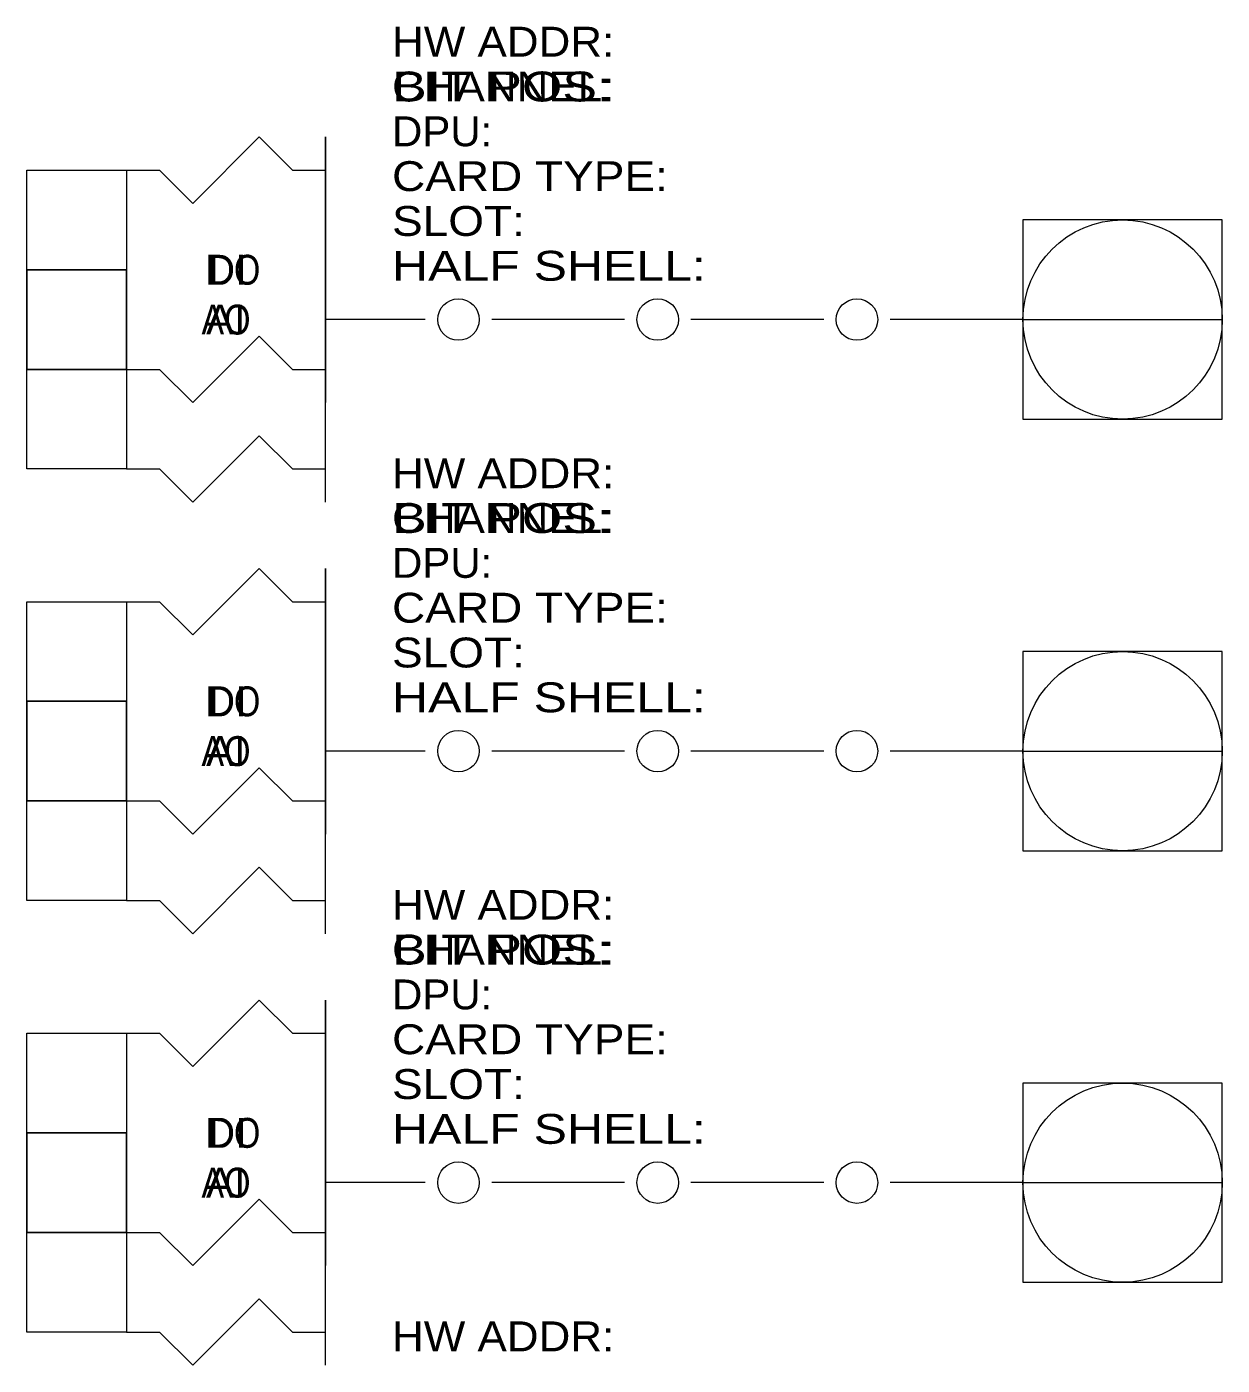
# Model space of a CAD drawing. Extents: x 0.958 to 1.258, y 0.171 to 0.832.
# Drawn here: x 0.9583 to 1.2583, y 0.4958 to 0.8318 of the extents above; entities that cross this region are included whole.
import ezdxf
from ezdxf.enums import TextEntityAlignment as Align

# ---------------------------------------------------------------- set-up
doc = ezdxf.new("R2010")
doc.units = 0
doc.header["$LTSCALE"] = 0.003
for name, color, linetype, lineweight in [('1', 7, 'Continuous', 13), ('10', 7, 'Continuous', 13), ('11', 7, 'Continuous', 13), ('12', 7, 'Continuous', 13), ('13', 7, 'Continuous', 13), ('14', 7, 'Continuous', 13), ('19', 7, 'Continuous', 13), ('2', 7, 'Continuous', 13), ('20', 7, 'Continuous', 13), ('21', 7, 'Continuous', 13), ('22', 7, 'Continuous', 13), ('23', 7, 'Continuous', 13), ('24', 7, 'Continuous', 13), ('29', 7, 'Continuous', 13), ('3', 7, 'Continuous', 13), ('30', 7, 'Continuous', 13), ('39', 7, 'Continuous', 13), ('4', 7, 'Continuous', 13), ('40', 7, 'Continuous', 13), ('9', 7, 'Continuous', 13)]:
    doc.layers.add(name, color=color, linetype=linetype, lineweight=lineweight)

msp = doc.modelspace()

# ---------------------------------------------------------------- linework, layer by layer
at = {"layer": '1'}
for p, q in [((1.033333, 0.804166), (1.033333, 0.7375)), ((0.958333, 0.770833), (0.958333, 0.745833)), ((0.983333, 0.745833), (0.983333, 0.770833)), ((0.958333, 0.745833), (0.983333, 0.745833))]:
    msp.add_line(p, q, dxfattribs=at)
for points in [[(0.983333, 0.795833), (0.991666, 0.795833), (1, 0.7875), (1.016666, 0.804166), (1.025, 0.795833), (1.033333, 0.795833)], [(0.983333, 0.745833), (0.991666, 0.745833), (1, 0.7375), (1.016666, 0.754166), (1.025, 0.745833), (1.033333, 0.745833)]]:
    msp.add_lwpolyline(points, dxfattribs=at)
msp.add_lwpolyline([(0.958333, 0.795833), (0.983333, 0.795833), (0.983333, 0.770833), (0.958333, 0.770833)], close=True, dxfattribs=at)
at = {"layer": '10'}
for p, q in [((1.058333, 0.758333), (1.033333, 0.758333)), ((1.108333, 0.758333), (1.075, 0.758333)), ((1.158333, 0.758333), (1.125, 0.758333)), ((1.208333, 0.758333), (1.175, 0.758333)), ((1.208333, 0.758333), (1.258333, 0.758333))]:
    msp.add_line(p, q, dxfattribs=at)
msp.add_lwpolyline([(1.208333, 0.783333), (1.208333, 0.733333), (1.258333, 0.733333), (1.258333, 0.783333)], close=True, dxfattribs=at)
for centre, radius in [((1.233333, 0.758333), 0.025), ((1.066666, 0.758333), 0.005208), ((1.116666, 0.758333), 0.005208), ((1.166666, 0.758333), 0.005208)]:
    msp.add_circle(centre, radius, dxfattribs=at)
at = {"layer": '11'}
msp.add_line((1.033333, 0.695833), (1.033333, 0.629166), dxfattribs=at)
for points in [[(0.983333, 0.6875), (0.991666, 0.6875), (1, 0.679166), (1.016666, 0.695833), (1.025, 0.6875), (1.033333, 0.6875)], [(0.958333, 0.6625), (0.958333, 0.6375), (0.983333, 0.6375), (0.983333, 0.6625)], [(0.983333, 0.6375), (0.991666, 0.6375), (1, 0.629166), (1.016666, 0.645833), (1.025, 0.6375), (1.033333, 0.6375)]]:
    msp.add_lwpolyline(points, dxfattribs=at)
msp.add_lwpolyline([(0.958333, 0.6875), (0.983333, 0.6875), (0.983333, 0.6625), (0.958333, 0.6625)], close=True, dxfattribs=at)
at = {"layer": '12'}
for p, q in [((1.033333, 0.695833), (1.033333, 0.629166)), ((0.958333, 0.6625), (0.983333, 0.6625))]:
    msp.add_line(p, q, dxfattribs=at)
for points in [[(0.983333, 0.6875), (0.991666, 0.6875), (1, 0.679166), (1.016666, 0.695833), (1.025, 0.6875), (1.033333, 0.6875)], [(0.983333, 0.6375), (0.991666, 0.6375), (1, 0.629166), (1.016666, 0.645833), (1.025, 0.6375), (1.033333, 0.6375)]]:
    msp.add_lwpolyline(points, dxfattribs=at)
msp.add_lwpolyline([(0.958333, 0.6875), (0.983333, 0.6875), (0.983333, 0.6375), (0.958333, 0.6375)], close=True, dxfattribs=at)
at = {"layer": '13'}
for p, q in [((1.033333, 0.604166), (1.033333, 0.695833)), ((0.958333, 0.6625), (0.983333, 0.6625)), ((0.958333, 0.6375), (0.983333, 0.6375))]:
    msp.add_line(p, q, dxfattribs=at)
for points in [[(0.983333, 0.6875), (0.991666, 0.6875), (1, 0.679166), (1.016666, 0.695833), (1.025, 0.6875), (1.033333, 0.6875)], [(0.983333, 0.6125), (0.991666, 0.6125), (1, 0.604166), (1.016666, 0.620833), (1.025, 0.6125), (1.033333, 0.6125)]]:
    msp.add_lwpolyline(points, dxfattribs=at)
msp.add_lwpolyline([(0.958333, 0.6875), (0.983333, 0.6875), (0.983333, 0.6125), (0.958333, 0.6125)], close=True, dxfattribs=at)
at = {"layer": '14'}
for p, q in [((1.033333, 0.604166), (1.033333, 0.695833)), ((0.958333, 0.6625), (0.983333, 0.6625)), ((0.958333, 0.6375), (0.983333, 0.6375))]:
    msp.add_line(p, q, dxfattribs=at)
for points in [[(0.983333, 0.6875), (0.991666, 0.6875), (1, 0.679166), (1.016666, 0.695833), (1.025, 0.6875), (1.033333, 0.6875)], [(0.983333, 0.6125), (0.991666, 0.6125), (1, 0.604166), (1.016666, 0.620833), (1.025, 0.6125), (1.033333, 0.6125)]]:
    msp.add_lwpolyline(points, dxfattribs=at)
msp.add_lwpolyline([(0.958333, 0.6875), (0.983333, 0.6875), (0.983333, 0.6125), (0.958333, 0.6125)], close=True, dxfattribs=at)
at = {"layer": '19'}
for p, q in [((1.058333, 0.65), (1.033333, 0.65)), ((1.108333, 0.65), (1.075, 0.65)), ((1.158333, 0.65), (1.125, 0.65)), ((1.208333, 0.65), (1.175, 0.65)), ((1.208333, 0.65), (1.258333, 0.65))]:
    msp.add_line(p, q, dxfattribs=at)
msp.add_lwpolyline([(1.208333, 0.675), (1.208333, 0.625), (1.258333, 0.625), (1.258333, 0.675)], close=True, dxfattribs=at)
for centre, radius in [((1.233333, 0.65), 0.025), ((1.066666, 0.65), 0.005208), ((1.116666, 0.65), 0.005208), ((1.166666, 0.65), 0.005208)]:
    msp.add_circle(centre, radius, dxfattribs=at)
at = {"layer": '2'}
for p, q in [((1.033333, 0.804166), (1.033333, 0.7375)), ((0.958333, 0.770833), (0.983333, 0.770833))]:
    msp.add_line(p, q, dxfattribs=at)
for points in [[(0.983333, 0.795833), (0.991666, 0.795833), (1, 0.7875), (1.016666, 0.804166), (1.025, 0.795833), (1.033333, 0.795833)], [(0.983333, 0.745833), (0.991666, 0.745833), (1, 0.7375), (1.016666, 0.754166), (1.025, 0.745833), (1.033333, 0.745833)]]:
    msp.add_lwpolyline(points, dxfattribs=at)
msp.add_lwpolyline([(0.958333, 0.795833), (0.983333, 0.795833), (0.983333, 0.745833), (0.958333, 0.745833)], close=True, dxfattribs=at)
at = {"layer": '20'}
for p, q in [((1.058333, 0.65), (1.033333, 0.65)), ((1.108333, 0.65), (1.075, 0.65)), ((1.158333, 0.65), (1.125, 0.65)), ((1.208333, 0.65), (1.175, 0.65)), ((1.208333, 0.65), (1.258333, 0.65))]:
    msp.add_line(p, q, dxfattribs=at)
msp.add_lwpolyline([(1.208333, 0.675), (1.208333, 0.625), (1.258333, 0.625), (1.258333, 0.675)], close=True, dxfattribs=at)
for centre, radius in [((1.233333, 0.65), 0.025), ((1.066666, 0.65), 0.005208), ((1.116666, 0.65), 0.005208), ((1.166666, 0.65), 0.005208)]:
    msp.add_circle(centre, radius, dxfattribs=at)
at = {"layer": '21'}
msp.add_line((1.033333, 0.5875), (1.033333, 0.520833), dxfattribs=at)
for points in [[(0.983333, 0.579166), (0.991666, 0.579166), (1, 0.570833), (1.016666, 0.5875), (1.025, 0.579166), (1.033333, 0.579166)], [(0.958333, 0.554166), (0.958333, 0.529166), (0.983333, 0.529166), (0.983333, 0.554166)], [(0.983333, 0.529166), (0.991666, 0.529166), (1, 0.520833), (1.016666, 0.5375), (1.025, 0.529166), (1.033333, 0.529166)]]:
    msp.add_lwpolyline(points, dxfattribs=at)
msp.add_lwpolyline([(0.958333, 0.579166), (0.983333, 0.579166), (0.983333, 0.554166), (0.958333, 0.554166)], close=True, dxfattribs=at)
at = {"layer": '22'}
for p, q in [((1.033333, 0.5875), (1.033333, 0.520833)), ((0.958333, 0.554166), (0.983333, 0.554166))]:
    msp.add_line(p, q, dxfattribs=at)
for points in [[(0.983333, 0.579166), (0.991666, 0.579166), (1, 0.570833), (1.016666, 0.5875), (1.025, 0.579166), (1.033333, 0.579166)], [(0.983333, 0.529166), (0.991666, 0.529166), (1, 0.520833), (1.016666, 0.5375), (1.025, 0.529166), (1.033333, 0.529166)]]:
    msp.add_lwpolyline(points, dxfattribs=at)
msp.add_lwpolyline([(0.958333, 0.579166), (0.983333, 0.579166), (0.983333, 0.529166), (0.958333, 0.529166)], close=True, dxfattribs=at)
at = {"layer": '23'}
for p, q in [((1.033333, 0.495833), (1.033333, 0.5875)), ((0.958333, 0.554166), (0.983333, 0.554166)), ((0.958333, 0.529166), (0.983333, 0.529166))]:
    msp.add_line(p, q, dxfattribs=at)
for points in [[(0.983333, 0.579166), (0.991666, 0.579166), (1, 0.570833), (1.016666, 0.5875), (1.025, 0.579166), (1.033333, 0.579166)], [(0.983333, 0.504166), (0.991666, 0.504166), (1, 0.495833), (1.016666, 0.5125), (1.025, 0.504166), (1.033333, 0.504166)]]:
    msp.add_lwpolyline(points, dxfattribs=at)
msp.add_lwpolyline([(0.958333, 0.579166), (0.983333, 0.579166), (0.983333, 0.504166), (0.958333, 0.504166)], close=True, dxfattribs=at)
at = {"layer": '24'}
for p, q in [((1.033333, 0.495833), (1.033333, 0.5875)), ((0.958333, 0.554166), (0.983333, 0.554166)), ((0.958333, 0.529166), (0.983333, 0.529166))]:
    msp.add_line(p, q, dxfattribs=at)
for points in [[(0.983333, 0.579166), (0.991666, 0.579166), (1, 0.570833), (1.016666, 0.5875), (1.025, 0.579166), (1.033333, 0.579166)], [(0.983333, 0.504166), (0.991666, 0.504166), (1, 0.495833), (1.016666, 0.5125), (1.025, 0.504166), (1.033333, 0.504166)]]:
    msp.add_lwpolyline(points, dxfattribs=at)
msp.add_lwpolyline([(0.958333, 0.579166), (0.983333, 0.579166), (0.983333, 0.504166), (0.958333, 0.504166)], close=True, dxfattribs=at)
at = {"layer": '29'}
for p, q in [((1.058333, 0.541666), (1.033333, 0.541666)), ((1.108333, 0.541666), (1.075, 0.541666)), ((1.158333, 0.541666), (1.125, 0.541666)), ((1.208333, 0.541666), (1.175, 0.541666)), ((1.208333, 0.541666), (1.258333, 0.541666))]:
    msp.add_line(p, q, dxfattribs=at)
msp.add_lwpolyline([(1.208333, 0.566666), (1.208333, 0.516666), (1.258333, 0.516666), (1.258333, 0.566666)], close=True, dxfattribs=at)
for centre, radius in [((1.233333, 0.541666), 0.025), ((1.066666, 0.541666), 0.005208), ((1.116666, 0.541666), 0.005208), ((1.166666, 0.541666), 0.005208)]:
    msp.add_circle(centre, radius, dxfattribs=at)
at = {"layer": '3'}
for p, q in [((1.033333, 0.7125), (1.033333, 0.804166)), ((0.958333, 0.770833), (0.983333, 0.770833)), ((0.958333, 0.745833), (0.983333, 0.745833))]:
    msp.add_line(p, q, dxfattribs=at)
for points in [[(0.983333, 0.795833), (0.991666, 0.795833), (1, 0.7875), (1.016666, 0.804166), (1.025, 0.795833), (1.033333, 0.795833)], [(0.983333, 0.720833), (0.991666, 0.720833), (1, 0.7125), (1.016666, 0.729166), (1.025, 0.720833), (1.033333, 0.720833)]]:
    msp.add_lwpolyline(points, dxfattribs=at)
msp.add_lwpolyline([(0.958333, 0.795833), (0.983333, 0.795833), (0.983333, 0.720833), (0.958333, 0.720833)], close=True, dxfattribs=at)
at = {"layer": '30'}
for p, q in [((1.058333, 0.541666), (1.033333, 0.541666)), ((1.108333, 0.541666), (1.075, 0.541666)), ((1.158333, 0.541666), (1.125, 0.541666)), ((1.208333, 0.541666), (1.175, 0.541666)), ((1.208333, 0.541666), (1.258333, 0.541666))]:
    msp.add_line(p, q, dxfattribs=at)
msp.add_lwpolyline([(1.208333, 0.566666), (1.208333, 0.516666), (1.258333, 0.516666), (1.258333, 0.566666)], close=True, dxfattribs=at)
for centre, radius in [((1.233333, 0.541666), 0.025), ((1.066666, 0.541666), 0.005208), ((1.116666, 0.541666), 0.005208), ((1.166666, 0.541666), 0.005208)]:
    msp.add_circle(centre, radius, dxfattribs=at)
at = {"layer": '4'}
for p, q in [((1.033333, 0.7125), (1.033333, 0.804166)), ((0.958333, 0.770833), (0.983333, 0.770833)), ((0.958333, 0.745833), (0.983333, 0.745833))]:
    msp.add_line(p, q, dxfattribs=at)
for points in [[(0.983333, 0.795833), (0.991666, 0.795833), (1, 0.7875), (1.016666, 0.804166), (1.025, 0.795833), (1.033333, 0.795833)], [(0.983333, 0.720833), (0.991666, 0.720833), (1, 0.7125), (1.016666, 0.729166), (1.025, 0.720833), (1.033333, 0.720833)]]:
    msp.add_lwpolyline(points, dxfattribs=at)
msp.add_lwpolyline([(0.958333, 0.795833), (0.983333, 0.795833), (0.983333, 0.720833), (0.958333, 0.720833)], close=True, dxfattribs=at)
at = {"layer": '9'}
for p, q in [((1.058333, 0.758333), (1.033333, 0.758333)), ((1.108333, 0.758333), (1.075, 0.758333)), ((1.158333, 0.758333), (1.125, 0.758333)), ((1.208333, 0.758333), (1.175, 0.758333)), ((1.208333, 0.758333), (1.258333, 0.758333))]:
    msp.add_line(p, q, dxfattribs=at)
msp.add_lwpolyline([(1.208333, 0.783333), (1.208333, 0.733333), (1.258333, 0.733333), (1.258333, 0.783333)], close=True, dxfattribs=at)
for centre, radius in [((1.233333, 0.758333), 0.025), ((1.066666, 0.758333), 0.005208), ((1.116666, 0.758333), 0.005208), ((1.166666, 0.758333), 0.005208)]:
    msp.add_circle(centre, radius, dxfattribs=at)

# ---------------------------------------------------------------- texts
at = {"layer": '1', "width": 1.05}
msp.add_text('DI', height=0.0075, dxfattribs=at).set_placement((1.008291, 0.767083), align=Align.CENTER)
at = {"layer": '10'}
for s, width, p in [('HW ADDR:', 1.1, (1.05, 0.824333)), ('CHANNEL:', 1.1, (1.05, 0.813083)), ('DPU:', 1.05, (1.05, 0.801833)), ('CARD TYPE:', 1.15, (1.05, 0.790583)), ('SLOT:', 1.15, (1.05, 0.779333)), ('HALF SHELL:', 1.25, (1.05, 0.768083))]:
    msp.add_text(s, height=0.0075, dxfattribs=dict(at, width=width)).set_placement(p)
at = {"layer": '11', "width": 1.05}
msp.add_text('DI', height=0.0075, dxfattribs=at).set_placement((1.008291, 0.65875), align=Align.CENTER)
at = {"layer": '12', "width": 0.85}
msp.add_text('DO', height=0.0075, dxfattribs=at).set_placement((1.004166, 0.65875))
at = {"layer": '13', "width": 1.05}
msp.add_text('AI', height=0.0075, dxfattribs=at).set_placement((1.008291, 0.64625), align=Align.CENTER)
at = {"layer": '14', "width": 0.85}
msp.add_text('AO', height=0.0075, dxfattribs=at).set_placement((1.008333, 0.64625), align=Align.CENTER)
at = {"layer": '19'}
for s, width, p in [('HW ADDR:', 1.1, (1.05, 0.716)), ('BIT POS:', 1.3, (1.05, 0.70475)), ('DPU:', 1.05, (1.05, 0.6935)), ('CARD TYPE:', 1.15, (1.05, 0.68225)), ('SLOT:', 1.15, (1.05, 0.671)), ('HALF SHELL:', 1.25, (1.05, 0.65975))]:
    msp.add_text(s, height=0.0075, dxfattribs=dict(at, width=width)).set_placement(p)
at = {"layer": '2', "width": 0.85}
msp.add_text('DO', height=0.0075, dxfattribs=at).set_placement((1.004166, 0.767083))
at = {"layer": '20'}
for s, width, p in [('HW ADDR:', 1.1, (1.05, 0.716)), ('CHANNEL:', 1.1, (1.05, 0.70475)), ('DPU:', 1.05, (1.05, 0.6935)), ('CARD TYPE:', 1.15, (1.05, 0.68225)), ('SLOT:', 1.15, (1.05, 0.671)), ('HALF SHELL:', 1.25, (1.05, 0.65975))]:
    msp.add_text(s, height=0.0075, dxfattribs=dict(at, width=width)).set_placement(p)
at = {"layer": '21', "width": 1.05}
msp.add_text('DI', height=0.0075, dxfattribs=at).set_placement((1.008291, 0.550416), align=Align.CENTER)
at = {"layer": '22', "width": 0.85}
msp.add_text('DO', height=0.0075, dxfattribs=at).set_placement((1.004166, 0.550416))
at = {"layer": '23', "width": 1.05}
msp.add_text('AI', height=0.0075, dxfattribs=at).set_placement((1.008291, 0.537916), align=Align.CENTER)
at = {"layer": '24', "width": 0.85}
msp.add_text('AO', height=0.0075, dxfattribs=at).set_placement((1.008333, 0.537916), align=Align.CENTER)
at = {"layer": '29'}
for s, width, p in [('HW ADDR:', 1.1, (1.05, 0.607666)), ('BIT POS:', 1.3, (1.05, 0.596416)), ('DPU:', 1.05, (1.05, 0.585166)), ('CARD TYPE:', 1.15, (1.05, 0.573916)), ('SLOT:', 1.15, (1.05, 0.562666)), ('HALF SHELL:', 1.25, (1.05, 0.551416))]:
    msp.add_text(s, height=0.0075, dxfattribs=dict(at, width=width)).set_placement(p)
at = {"layer": '3', "width": 1.05}
msp.add_text('AI', height=0.0075, dxfattribs=at).set_placement((1.008291, 0.754583), align=Align.CENTER)
at = {"layer": '30'}
for s, width, p in [('HW ADDR:', 1.1, (1.05, 0.607666)), ('CHANNEL:', 1.1, (1.05, 0.596416)), ('DPU:', 1.05, (1.05, 0.585166)), ('CARD TYPE:', 1.15, (1.05, 0.573916)), ('SLOT:', 1.15, (1.05, 0.562666)), ('HALF SHELL:', 1.25, (1.05, 0.551416))]:
    msp.add_text(s, height=0.0075, dxfattribs=dict(at, width=width)).set_placement(p)
at = {"layer": '39', "width": 1.1}
msp.add_text('HW ADDR:', height=0.0075, dxfattribs=at).set_placement((1.05, 0.499333))
at = {"layer": '4', "width": 0.85}
msp.add_text('AO', height=0.0075, dxfattribs=at).set_placement((1.008333, 0.754583), align=Align.CENTER)
at = {"layer": '40', "width": 1.1}
msp.add_text('HW ADDR:', height=0.0075, dxfattribs=at).set_placement((1.05, 0.499333))
at = {"layer": '9'}
for s, width, p in [('HW ADDR:', 1.1, (1.05, 0.824333)), ('BIT POS:', 1.3, (1.05, 0.813083)), ('DPU:', 1.05, (1.05, 0.801833)), ('CARD TYPE:', 1.15, (1.05, 0.790583)), ('SLOT:', 1.15, (1.05, 0.779333)), ('HALF SHELL:', 1.25, (1.05, 0.768083))]:
    msp.add_text(s, height=0.0075, dxfattribs=dict(at, width=width)).set_placement(p)

doc.saveas('drawing.dxf')
